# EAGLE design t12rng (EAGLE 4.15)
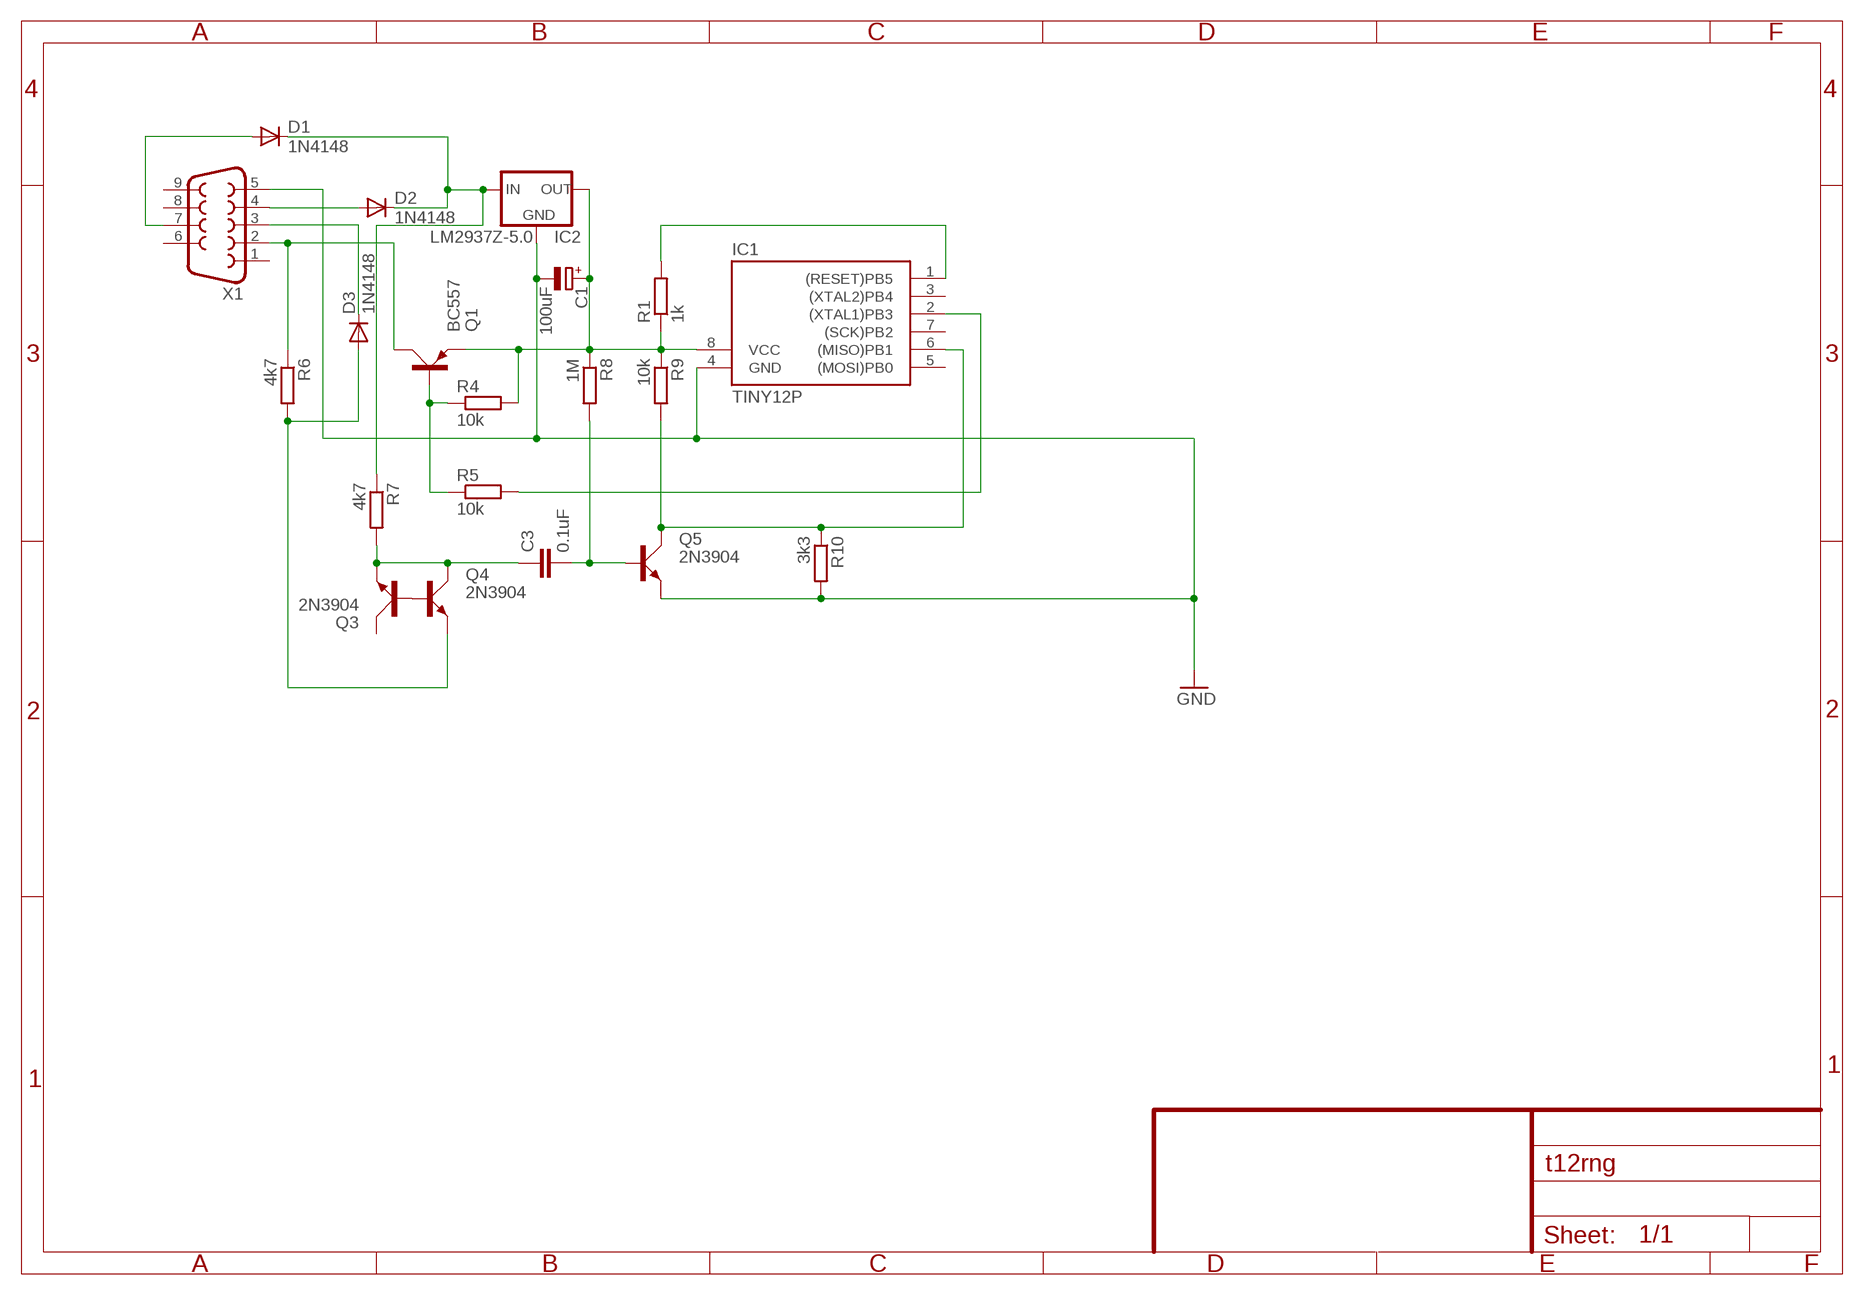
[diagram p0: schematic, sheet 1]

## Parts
C1  100uF  CPOL-EUE3.5-8  [E3,5-8]
C3  0.1uF  C-EU075-032X103  [C075-032X103]
D1  1N4148  DIODE-D-2.5  [D-2.5]
D2  1N4148  DIODE-D-2.5  [D-2.5]
D3  1N4148  DIODE-D-2.5  [D-2.5]
IC1  TINY12P  [DIL08]
IC2  LM2937Z-5.0  78LXX  [78LXX]
Q1  BC557  [SOT54A]
Q3  2N3904  [TO92D]
Q4  2N3904  [TO92D]
Q5  2N3904  [TO92D]
R1  1k  R-EU_0207/2V  [0207/2V]
R4  10k  R-EU_0207/2V  [0207/2V]
R5  10k  R-EU_0207/2V  [0207/2V]
R6  4k7  R-EU_0207/2V  [0207/2V]
R7  4k7  R-EU_0207/2V  [0207/2V]
R8  1M  R-EU_0207/2V  [0207/2V]
R9  10k  R-EU_0207/2V  [0207/2V]
R10  3k3  R-EU_0207/2V  [0207/2V]
X1  F09H  [F09H]

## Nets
GND: C1.- IC1.4(GND) IC2.GND Q5.E R10.2 X1.5
N$3: D1.A X1.7
N$4: D2.A X1.4
N$5: D1.C D2.C IC2.IN R7.1
N$6: C1.+ IC1.8(VCC) IC2.OUT Q1.E R1.1 R4.2 R8.1 R9.1
N$7: IC1.1((RESET)PB5) R1.2
N$9: D3.A Q4.E R6.2
N$10: Q1.B R4.1 R5.1
N$11: IC1.2((XTAL1)PB3) R5.2
N$12: Q1.C R6.1 X1.2
N$13: D3.C X1.3
N$14: Q3.B Q4.B
N$15: C3.1 Q3.E Q4.C R7.2
N$17: C3.2 Q5.B R8.2
N$18: IC1.6((MISO)PB1) Q5.C R9.2 R10.1
Unconnected: IC1.3((XTAL2)PB4) IC1.5((MOSI)PB0) IC1.7((SCK)PB2) Q3.C X1.1 X1.6 X1.8 X1.9

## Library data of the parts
C1 = rcl:CPOL-EU: POLARIZED CAPACITOR, European symbol
C3 = rcl:C-EU: CAPACITOR, European symbol
D1-D3 = diode:DIODE-: DIODE
IC1 = atmel:TINY12*: MICROCONTROLLER 1 Kbytes FLASH 64 bytes EEPROM
IC2 = v-reg:78LXX: VOLTAGE REGULATOR
Q1 = transistor-small-signal:BC557: PNP TRANSISTOR
Q3-Q5 = transistor-small-signal:2N3904: NPN TRANSISTOR
R1 R4-R10 = rcl:R-EU_: RESISTOR, European symbol
X1 = con-subd:F09: SUB-D

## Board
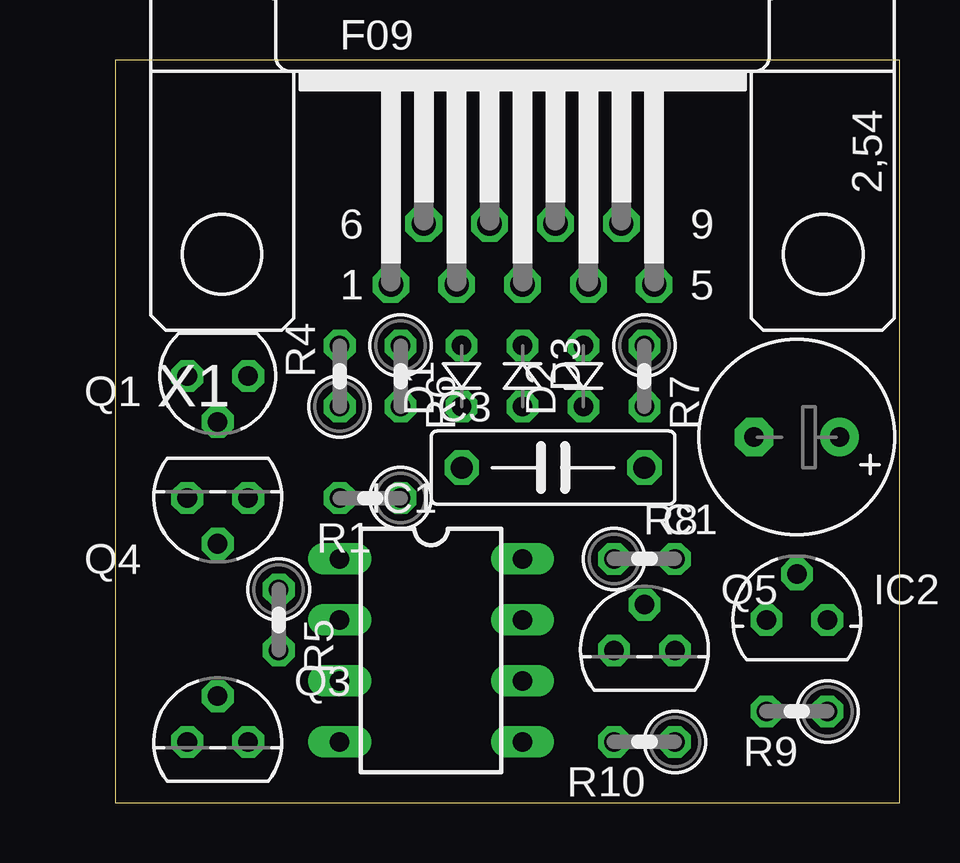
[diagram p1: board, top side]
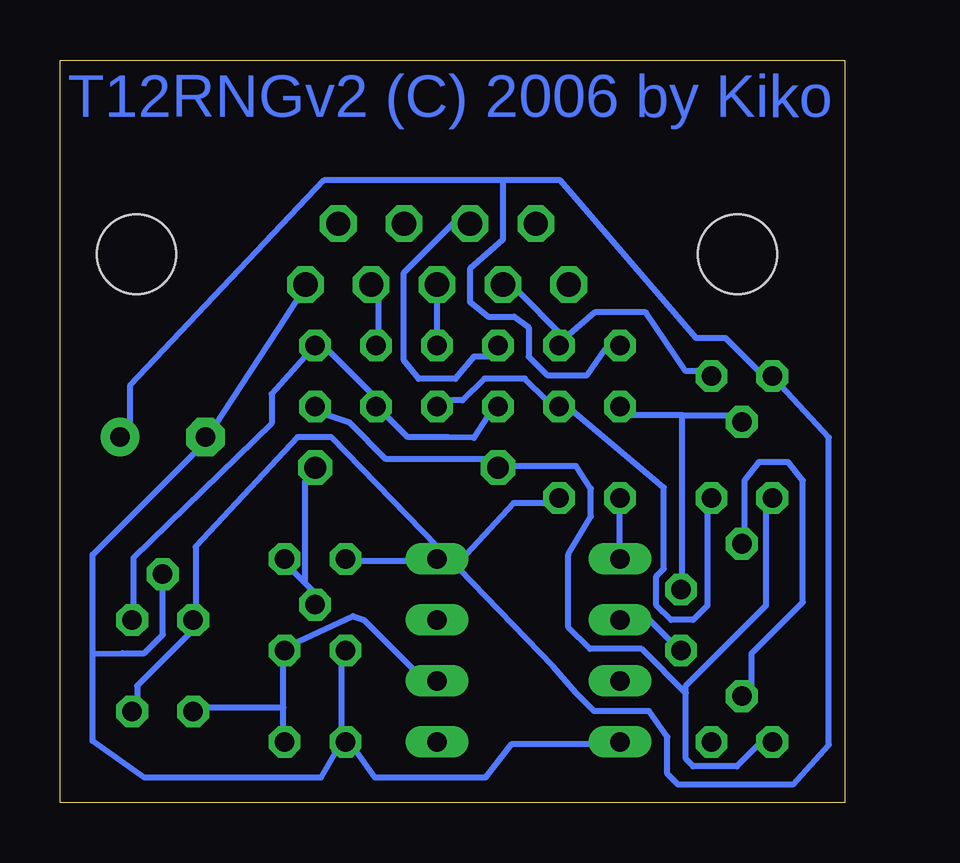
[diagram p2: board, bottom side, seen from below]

Size 32.69 x 30.95 mm. Coordinates in mm from the lower left corner, seen from the top.
Outline: 0,0 32.69,0 32.69,30.95 0,30.95 0,0
Copper layers (1*16): Top 0.035mm / dielectric 1.5mm / Bottom 0.035mm
Design rules "default": minimum track width 10mil, minimum drill 24mil, track to track 8mil, track to pad 8mil, pad to pad 8mil, via to via 8mil, smd to smd 8mil, copper to edge 40mil, drill to drill 8mil, minimum pad ring 10mil, minimum via ring 8mil, stop-mask expansion 4mil, vias tented up to drill 0mil, thermal gap 10mil

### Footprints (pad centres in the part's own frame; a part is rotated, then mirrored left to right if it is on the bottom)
E3,5-8 = drill 0.813 pad 1.6 round: + -1.778,0 | drill 0.813 pad 1.6 octagon: - 1.778,0
C075-032X103 = drill 0.914 octagon: 1 -3.81,0; 2 3.81,0
D-2.5 = drill 0.813 octagon: A 1.27,0; C -1.27,0
DIL08 = drill 0.813 long: 1 -3.81,-3.81; 2 -1.27,-3.81; 3 1.27,-3.81; 4 3.81,-3.81; 5 3.81,3.81; 6 1.27,3.81; 7 -1.27,3.81; 8 -3.81,3.81
78LXX = drill 0.813 octagon: GND 0,1.905; IN 1.27,0; OUT -1.27,0
SOT54A = drill 0.813 octagon: B 0,1.905; C -1.27,0; E 1.27,0
TO92D = drill 0.813 octagon: B 0,1.905; C 1.27,0; E -1.27,0
0207/2V = drill 0.813 octagon: 1 -1.27,0; 2 1.27,0
F09H = drill 1.016 octagon: 1 -5.486,-1.27; 2 -2.743,-1.27; 3 0,-1.27; 4 2.743,-1.27; 5 5.486,-1.27; 6 -4.115,1.27; 7 -1.372,1.27; 8 1.372,1.27; 9 4.115,1.27 | hole 3.302: -12.522,0; 12.522,0

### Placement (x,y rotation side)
C1  28.41,15.23 180 top
C3  18.25,13.96 0 top
D1  14.44,17.77 90 top
D2  19.52,17.77 90 top
D3  16.98,17.77 270 top
IC1  13.17,6.34 270 top
IC2  28.41,7.62 0 top
Q1  4.28,17.77 180 top
Q3  4.28,2.53 0 top
Q4  4.28,12.7 180 top
Q5  22.06,6.34 0 top
R1  10.63,12.7 180 top
R4  9.36,17.77 90 top
R5  6.82,7.62 270 top
R6  11.9,17.77 270 top
R7  22.06,17.77 270 top
R8  22.06,10.16 0 top
R9  28.41,3.8 180 top
R10  22.06,2.53 180 top
X1  16.98,22.85 0 top

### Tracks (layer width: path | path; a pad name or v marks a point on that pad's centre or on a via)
GND
  Bottom 0.254: IC1.4 10.58,2.43 13.89,2.43 14.97,1.04 19.56,1.04 20.33,2.13 R10.2 | Q5.E 20.94,5.79 20.94,3.04 R10.2 | 31.33,6.21 30.09,6.24 29.17,6.24 28.4,7 28.4,9.46 IC2.GND | 31.33,6.21 31.33,10.33 27.04,14.62 C1.- 26.24,15.69 23.25,20.27 22.77,21.03 X1.5 | 31.33,6.21 31.33,2.57 29.17,1.04 21.82,1.04 21.21,2.13 21.25,2.13 R10.2
N$3
  Bottom 0.254: D1.A 14.85,18.59 15.44,18.59 16.21,17.66 17.75,17.66 18.36,18.43 18.36,22.09 16.07,24.38 X1.7
N$4
  Bottom 0.254: D2.A 19.42,19.5 19.42,21.03 X1.4
N$5
  Bottom 0.254: D1.C 14.85,16.15 15.44,15.2 16.52,15.23 18.2,15.23 19.11,16.15 D2.C 19.72,17.06 21.55,18.89 R7.1 22.47,18.59 23.87,17.03 23.87,15.81 29.63,10.2 29.63,8.07 IC2.IN
N$6
  Bottom 0.254: R9.1 29.48,4.26 29.48,4.87 27.34,7 IC2.OUT 27.04,8.23 27.04,10.66 22.78,15.23 21.39,15.23 16.98,10.66 IC1.8 | IC1.8 18.2,10.05 20.33,10.05 R8.1 | R1.1 12.41,12.49 13.79,12.49 15.76,10.36 IC1.8 | 14.24,25.93 21.7,25.93 29.78,17.37 29.78,15.84 C1.+ | 14.24,25.93 11.84,25.93 6.19,19.36 4.95,19.36 3.57,17.98 Q1.E 2.65,17.37 0.65,15.21 0.65,2.42 2.17,0.75 6.93,0.75 7.38,1.2 7.38,2.74 8.14,3.81 10.43,3.81 11.19,4.57 12.14,5.67 16.07,9.75 IC1.8 | 14.24,25.93 14.24,23.46 15.62,22.24 15.62,20.87 14.85,20.26 13.77,20.26 13.16,19.81 13.16,18.59 12.39,17.82 10.72,17.82 9.97,18.89 R4.2
N$7
  Bottom 0.254: IC1.1 R1.2
N$9
  Bottom 0.254: Q4.E 5.7,12.19 5.7,8.23 6.31,7.62 7.23,7.62 7.84,8.23 7.84,9.44 7.53,9.75 7.53,13.13 11.49,16.45 R6.2 12.41,16.76 13.32,17.67 15.01,17.67 15.92,16.76 16.37,16.76 D3.A
N$10
  Bottom 0.254: 6.76,16.15 9.05,16.15 R4.1 | 6.76,16.15 4.79,16.15 Q1.B | 6.76,16.15 6.76,9.44 R5.1
N$11
  Bottom 0.254: R5.2 7.23,6.7 8.14,7.62 IC1.2
N$12
  Bottom 0.254: Q1.C 6.01,17.98 6.62,17.98 8.27,20.43 10.41,20.43 11.49,19.5 R6.1 11.8,19.5 13.63,21.33 X1.2
N$13
  Bottom 0.254: D3.C X1.3
N$14
  Bottom 0.254: Q3.B 3.87,4.87 3.87,6.22 1.74,8.36 1.74,13.42 2.35,14.19 3.57,14.19 4.18,13.42 4.18,11.27 Q4.B
N$15
  Bottom 0.254: R7.2 21.55,16.15 20.62,15.83 19.11,14.32 14.85,14.32 C3.1 13.93,14.03 11.19,14.03 10.57,13.09 10.57,11.92 11.51,10.35 11.51,7.31 10.61,6.41 8.46,6.41 6.62,4.57 | 6.62,4.57 6.62,4.87 3.26,8.23 3.26,12.19 Q4.C | 6.62,4.57 6.62,1.82 6.31,1.52 4.48,1.52 3.57,2.43 Q3.E
N$17
  Bottom 0.254: 22.47,9.14 23.08,9.75 R8.2 | 22.47,9.14 22.16,8.83 Q5.B | 22.47,9.14 22.47,13.41 C3.2
N$18
  Bottom 0.254: IC1.6 17.89,5.48 20.03,7.62 20.47,7.77 22.77,6.7 Q5.C 23.38,5.79 23.38,3.96 | 23.38,3.96 23.38,3.04 R10.1 | 23.38,3.96 26.73,3.96 R9.2

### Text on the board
Bottom: T12RNGv2 (C) 2006 by Kiko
